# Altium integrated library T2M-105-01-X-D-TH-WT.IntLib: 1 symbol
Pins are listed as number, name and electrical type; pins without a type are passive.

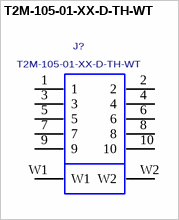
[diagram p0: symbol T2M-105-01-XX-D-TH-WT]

## T2M-105-01-XX-D-TH-WT
designator J?
2MM PITCH SHROUDED TERMINAL STRIP, 10PINS.; MANUFACTURER: SAMTEC
footprint T2M-105-01-XX-D-TH-WT
pins: 1, 2, 3, 4, 5, 6, 7, 8, 9, 10, W1, W2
